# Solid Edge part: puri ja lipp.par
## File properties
Username: Kasutaja
Author: Kasutaja
Template: Iso Metric Part.par
Last saved by: Kasutaja
Revision: 12
Application: Solid Edge
Accuracy: 0,990
Face Style: Model Default
Fill Style: Normal
Coef. of Thermal Exp: 0.0
Thermal Conductivity: 0.0
Specific Heat: 0.0
Modulus of Elasticity: 0.0
Poisson's Ratio: 0.0
Yield Stress: 0.0
Ultimate Stress: 0.0
Elongation: 0.0
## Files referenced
..\Raemapuu.par.asm
?C:\Users\Kasutaja\Desktop\ema asjad\New folder\Raemapuu.par.asm
C:\Users\Kasutaja\Desktop\ema asjad\New folder\vedru.par
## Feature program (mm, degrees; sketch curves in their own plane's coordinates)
sketch for "unnamed Protrusion 1" plane through (0, 0, 0) normal (0, -1, 0) x-axis (1, 0, 0)
  line (-43.6871, 422.4607) -> (68.138, 376.9726)
  line (68.138, 376.9726) -> (-43.6871, 376.9726)
  line (-43.6871, 376.9726) -> (-43.6871, 422.4607)
extrude "unnamed Protrusion 1" add finite 3 along +normal
sketch for "ExtrudedCutout_1" #1 plane through (12.2254, 0, 399.7167) normal (0, 1, 0) x-axis (-1, 0, 0)
  circle centre (49.8132, 13.2316) radius 3
sketch for "ExtrudedCutout_1" #2 plane through (12.2254, 0, 399.7167) normal (0, 1, 0) x-axis (-1, 0, 0)
  circle centre (49.8132, -16.172) radius 3
extrude "ExtrudedCutout_1" cut finite 4 along -normal
sketch for "unnamed RevolvedProtrusion 1" plane through (12.2254, 0, 399.7167) normal (0, 1, 0) x-axis (1, 0, 0)
  line (-49.8823, 18.4105) -> (-49.8823, 13.9056)
revolve "unnamed RevolvedProtrusion 1" add finite 360 deg
thicken "Thicken_2"  Distance1 = 2 mm
sketch for "ExtrudedCutout_3" #1 plane through (0, -164.6196, 0) normal (0, -1, 0) x-axis (1, 0, 0)
sketch for "ExtrudedCutout_3" #2 plane through (0, -164.6196, 0) normal (0, -1, 0) x-axis (1, 0, 0)
  circle centre (-228.1109, 343.8791) radius 3
sketch for "ExtrudedCutout_3" #3 plane through (0, -164.6196, 0) normal (0, -1, 0) x-axis (1, 0, 0)
  circle centre (-184.0316, 343.8791) radius 3
sketch for "ExtrudedCutout_3" #4 plane through (0, -164.6196, 0) normal (0, -1, 0) x-axis (1, 0, 0)
  circle centre (-139.3041, 343.8791) radius 3
sketch for "ExtrudedCutout_3" #5 plane through (0, -164.6196, 0) normal (0, -1, 0) x-axis (1, 0, 0)
  circle centre (-94.5766, 343.2957) radius 3
sketch for "ExtrudedCutout_3" #6 plane through (0, -164.6196, 0) normal (0, -1, 0) x-axis (1, 0, 0)
  circle centre (-49.8491, 343.7819) radius 3
sketch for "ExtrudedCutout_3" #7 plane through (0, -164.6196, 0) normal (0, -1, 0) x-axis (1, 0, 0)
  circle centre (-5.2837, 343.7819) radius 3
sketch for "ExtrudedCutout_3" #8 plane through (0, -164.6196, 0) normal (0, -1, 0) x-axis (1, 0, 0)
  circle centre (39.4438, 343.7819) radius 3
sketch for "ExtrudedCutout_3" #9 plane through (0, -164.6196, 0) normal (0, -1, 0) x-axis (1, 0, 0)
  circle centre (83.6851, 343.7819) radius 3
sketch for "ExtrudedCutout_3" #10 plane through (0, -164.6196, 0) normal (0, -1, 0) x-axis (1, 0, 0)
  circle centre (128.4126, 343.1337) radius 3
sketch for "ExtrudedCutout_3" #11 plane through (0, -164.6196, 0) normal (0, -1, 0) x-axis (1, 0, 0)
  circle centre (171.3575, 344.9163) radius 3
extrude "ExtrudedCutout_3" cut finite 551.5036 along -normal  Profile_Plane1_Distance = 164.6196 mm
mirror "unnamed Mirror 1" of "unnamed RevolvedProtrusion 1" about plane through (0, 0, 398.4228) normal (0, 0, 1)
revolve "unnamed RevolvedProtrusion 2" add finite 360 deg
sketch for "unnamed Protrusion 2" #1 plane through (0, -100, 0) normal (0, -1, 0) x-axis (1, 0, 0)
sketch for "unnamed Protrusion 2" #2 plane through (0, -100, 0) normal (0, -1, 0) x-axis (1, 0, 0)
sketch for "unnamed Protrusion 2" #3 plane through (0, -100, 0) normal (0, -1, 0) x-axis (1, 0, 0)
sketch for "unnamed Protrusion 2" #4 plane through (0, -100, 0) normal (0, -1, 0) x-axis (1, 0, 0)
sketch for "unnamed Protrusion 2" #5 plane through (0, -100, 0) normal (0, -1, 0) x-axis (1, 0, 0)
sketch for "unnamed Protrusion 2" #6 plane through (0, -100, 0) normal (0, -1, 0) x-axis (1, 0, 0)
sketch for "unnamed Protrusion 2" #7 plane through (0, -100, 0) normal (0, -1, 0) x-axis (1, 0, 0)
sketch for "unnamed Protrusion 2" #8 plane through (0, -100, 0) normal (0, -1, 0) x-axis (1, 0, 0)
sketch for "unnamed Protrusion 2" #9 plane through (0, -100, 0) normal (0, -1, 0) x-axis (1, 0, 0)
sketch for "unnamed Protrusion 2" #10 plane through (0, -100, 0) normal (0, -1, 0) x-axis (1, 0, 0)
sketch for "unnamed Protrusion 2" #11 plane through (0, -100, 0) normal (0, -1, 0) x-axis (1, 0, 0)
sketch for "unnamed Protrusion 2" #12 plane through (0, -100, 0) normal (0, -1, 0) x-axis (1, 0, 0)
extrude "unnamed Protrusion 2" add along -normal
Other named dimensions: "OffsetSurface_1": Distance = 0.5 mm | "OffsetSurface_2": Distance = 0.001 mm
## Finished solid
Body 1: sheet body, 1 face, 6 edges, 6 vertices.
  Faces by surface: offset 1
  Edges by curve: curve on surface 6
Body 2: sheet body, 1 face, 6 edges, 6 vertices.
  Faces by surface: offset 1
  Edges by curve: curve on surface 6
Body 3: sheet body, 1 face, 4 edges, 4 vertices.
  Faces by surface: spline 1
  Edges by curve: line 2, spline 2
Body 4: solid body, 128 faces, 290 edges, 172 vertices, 14 separate solids.
  Faces by surface: plane 72, offset 21, cylinder 15, swept 12, spline 6, torus 2
  Edges by curve: intersection 182, line 88, curve on surface 9, circle 8, spline 3
Bounding box of the edges (mm; curved faces can reach further): 473.670 x 56.458 x 302.777, from (-297.1393, -47.3569, 119.6834) to (176.5304, 9.101, 422.4607).
Cylindrical faces by radius (mm): R3 x13, R9.101 x2
Toroidal faces (ring radius, tube radius in mm): R9.101 r2.2524 x2
Planar faces by outward normal: +x 17, +y 1, +z 13, -x 11, -y 1, -z 14, oblique 15
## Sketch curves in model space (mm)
spline (102.6112, -100, 229.2776) -> (96.9577, -100, 229.2776) -> (91.3041, -100, 229.2776)
spline (102.6112, -100, 222.0657) -> (102.6112, -100, 225.6717) -> (102.6112, -100, 229.2776)
spline (102.4309, -100, 240.7135) -> (77.2102, -100, 232.4814) -> (102.6112, -100, 222.0657)
spline (107.1701, -100, 241.9756) -> (104.8005, -100, 241.3445) -> (102.4309, -100, 240.7135)
spline (107.7625, -100, 219.5158) -> (71.9767, -100, 235.1939) -> (107.1701, -100, 241.9756)
spline (107.7625, -100, 233.8365) -> (107.7625, -100, 226.6762) -> (107.7625, -100, 219.5158)
spline (91.3041, -100, 233.8365) -> (99.5333, -100, 233.8365) -> (107.7625, -100, 233.8365)
spline (91.3041, -100, 229.2776) -> (91.3041, -100, 231.557) -> (91.3041, -100, 233.8365)
spline (60.4992, -100, 229.2776) -> (54.8456, -100, 229.2776) -> (49.192, -100, 229.2776)
spline (60.4992, -100, 222.0657) -> (60.4992, -100, 225.6717) -> (60.4992, -100, 229.2776)
spline (60.3189, -100, 240.7135) -> (35.0983, -100, 232.4755) -> (60.4992, -100, 222.0657)
spline (65.0323, -100, 241.9756) -> (62.6756, -100, 241.3445) -> (60.3189, -100, 240.7135)
spline (65.6505, -100, 219.5158) -> (29.8592, -100, 235.4281) -> (65.0323, -100, 241.9756)
spline (65.6505, -100, 233.8365) -> (65.6505, -100, 226.6762) -> (65.6505, -100, 219.5158)
spline (49.192, -100, 233.8365) -> (57.4213, -100, 233.8365) -> (65.6505, -100, 233.8365)
spline (49.192, -100, 229.2776) -> (49.192, -100, 231.557) -> (49.192, -100, 233.8365)
closed spline through (-7.2922, -100, 232.9093), (6.6013, -100, 217.9076), (19.1845, -100, 233.7056), (5.3058, -100, 249.0747)
closed spline through (-12.5723, -100, 232.9608), (5.3917, -100, 253.4792), (24.4844, -100, 234.0594), (6.3601, -100, 213.4929)
spline (-44.8196, -100, 248.595) -> (-44.8196, -100, 242.143) -> (-44.8196, -100, 235.691)
spline (-44.8196, -100, 235.691) -> (-24.369, -100, 242.3129) -> (-44.8196, -100, 248.595)
spline (-44.8196, -100, 214.1327) -> (-47.3952, -100, 214.1327) -> (-49.9709, -100, 214.1327)
spline (-44.8196, -100, 231.2866) -> (-44.8196, -100, 222.7096) -> (-44.8196, -100, 214.1327)
spline (-22.334, -100, 214.1327) -> (-30.9125, -100, 227.1807) -> (-44.8196, -100, 231.2866)
spline (-15.9206, -100, 214.1327) -> (-19.1273, -100, 214.1327) -> (-22.334, -100, 214.1327)
spline (-29.958, -100, 231.6729) -> (-22.0309, -100, 223.7457) -> (-15.9206, -100, 214.1327)
spline (-49.9709, -100, 252.8449) -> (-23.3958, -100, 250.9847) -> (-29.958, -100, 231.6729)
spline (-49.9709, -100, 214.1327) -> (-49.9709, -100, 233.4888) -> (-49.9709, -100, 252.8449)
spline (-81.3939, -100, 214.1327) -> (-83.9696, -100, 214.1327) -> (-86.5452, -100, 214.1327)
spline (-81.3939, -100, 227.5261) -> (-81.3939, -100, 220.8294) -> (-81.3939, -100, 214.1327)
spline (-75.032, -100, 233.682) -> (-78.213, -100, 230.604) -> (-81.3939, -100, 227.5261)
spline (-61.278, -100, 214.1327) -> (-68.155, -100, 223.9073) -> (-75.032, -100, 233.682)
spline (-54.5298, -100, 214.1327) -> (-57.9039, -100, 214.1327) -> (-61.278, -100, 214.1327)
spline (-71.4261, -100, 237.1591) -> (-62.978, -100, 225.6459) -> (-54.5298, -100, 214.1327)
spline (-55.251, -100, 252.8449) -> (-63.3385, -100, 245.002) -> (-71.4261, -100, 237.1591)
spline (-62.2053, -100, 252.8449) -> (-58.7281, -100, 252.8449) -> (-55.251, -100, 252.8449)
spline (-81.3939, -100, 233.682) -> (-71.7996, -100, 243.2634) -> (-62.2053, -100, 252.8449)
spline (-81.3939, -100, 252.8449) -> (-81.3939, -100, 243.2634) -> (-81.3939, -100, 233.682)
spline (-86.5452, -100, 252.8449) -> (-83.9696, -100, 252.8449) -> (-81.3939, -100, 252.8449)
spline (-86.5452, -100, 214.1327) -> (-86.5452, -100, 233.4888) -> (-86.5452, -100, 252.8449)
spline (-99.4493, -100, 241.5377) -> (-95.6892, -100, 231.4604) -> (-124.0726, -100, 226.6246)
spline (-94.5555, -100, 241.9498) -> (-97.0024, -100, 241.7438) -> (-99.4493, -100, 241.5377)
spline (-119.2819, -100, 227.0368) -> (-116.8807, -100, 234.2416) -> (-94.5555, -100, 241.9498)
spline (-124.0726, -100, 226.6246) -> (-121.6772, -100, 226.8307) -> (-119.2819, -100, 227.0368)
spline (-128.5027, -100, 214.1327) -> (-140.6083, -100, 214.1327) -> (-152.7139, -100, 214.1327)
spline (-128.5027, -100, 218.6916) -> (-128.5027, -100, 216.4122) -> (-128.5027, -100, 214.1327)
spline (-147.5884, -100, 218.6916) -> (-138.0456, -100, 218.6916) -> (-128.5027, -100, 218.6916)
spline (-147.5884, -100, 252.8449) -> (-147.5884, -100, 235.7682) -> (-147.5884, -100, 218.6916)
spline (-152.7139, -100, 252.8449) -> (-150.1512, -100, 252.8449) -> (-147.5884, -100, 252.8449)
spline (-152.7139, -100, 214.1327) -> (-152.7139, -100, 233.4888) -> (-152.7139, -100, 252.8449)
spline (-158.5865, -100, 214.1327) -> (-170.6921, -100, 214.1327) -> (-182.7977, -100, 214.1327)
spline (-158.5865, -100, 218.6916) -> (-158.5865, -100, 216.4122) -> (-158.5865, -100, 214.1327)
spline (-177.6721, -100, 218.6916) -> (-168.1293, -100, 218.6916) -> (-158.5865, -100, 218.6916)
spline (-177.6721, -100, 252.8449) -> (-177.6721, -100, 235.7682) -> (-177.6721, -100, 218.6916)
spline (-182.7977, -100, 252.8449) -> (-180.2349, -100, 252.8449) -> (-177.6721, -100, 252.8449)
spline (-182.7977, -100, 214.1327) -> (-182.7977, -100, 233.4888) -> (-182.7977, -100, 252.8449)
spline (-189.6232, -100, 214.1327) -> (-204.0597, -100, 214.1327) -> (-218.4963, -100, 214.1327)
spline (-189.6232, -100, 218.6916) -> (-189.6232, -100, 216.4122) -> (-189.6232, -100, 214.1327)
spline (-213.3707, -100, 218.6916) -> (-201.4969, -100, 218.6916) -> (-189.6232, -100, 218.6916)
spline (-213.3707, -100, 231.8532) -> (-213.3707, -100, 225.2724) -> (-213.3707, -100, 218.6916)
spline (-191.9413, -100, 231.8532) -> (-202.656, -100, 231.8532) -> (-213.3707, -100, 231.8532)
spline (-191.9413, -100, 236.4122) -> (-191.9413, -100, 234.1327) -> (-191.9413, -100, 231.8532)
spline (-213.3707, -100, 236.4122) -> (-202.656, -100, 236.4122) -> (-191.9413, -100, 236.4122)
spline (-213.3707, -100, 248.2602) -> (-213.3707, -100, 242.3362) -> (-213.3707, -100, 236.4122)
spline (-190.4989, -100, 248.2602) -> (-201.9348, -100, 248.2602) -> (-213.3707, -100, 248.2602)
spline (-190.4989, -100, 252.8449) -> (-190.4989, -100, 250.5525) -> (-190.4989, -100, 248.2602)
spline (-218.4963, -100, 252.8449) -> (-204.4976, -100, 252.8449) -> (-190.4989, -100, 252.8449)
spline (-218.4963, -100, 214.1327) -> (-218.4963, -100, 233.4888) -> (-218.4963, -100, 252.8449)
spline (-249.8678, -100, 214.1327) -> (-252.4306, -100, 214.1327) -> (-254.9934, -100, 214.1327)
spline (-249.8678, -100, 227.5261) -> (-249.8678, -100, 220.8294) -> (-249.8678, -100, 214.1327)
spline (-243.506, -100, 233.682) -> (-246.6869, -100, 230.604) -> (-249.8678, -100, 227.5261)
spline (-229.7519, -100, 214.1327) -> (-236.629, -100, 223.9073) -> (-243.506, -100, 233.682)
spline (-223.0037, -100, 214.1327) -> (-226.3778, -100, 214.1327) -> (-229.7519, -100, 214.1327)
spline (-239.9, -100, 237.1591) -> (-231.4519, -100, 225.6459) -> (-223.0037, -100, 214.1327)
spline (-223.7249, -100, 252.8449) -> (-231.8125, -100, 245.002) -> (-239.9, -100, 237.1591)
spline (-230.6534, -100, 252.8449) -> (-227.1892, -100, 252.8449) -> (-223.7249, -100, 252.8449)
spline (-249.8678, -100, 233.682) -> (-240.2606, -100, 243.2634) -> (-230.6534, -100, 252.8449)
spline (-249.8678, -100, 252.8449) -> (-249.8678, -100, 243.2634) -> (-249.8678, -100, 233.682)
spline (-254.9934, -100, 252.8449) -> (-252.4306, -100, 252.8449) -> (-249.8678, -100, 252.8449)
spline (-254.9934, -100, 214.1327) -> (-254.9934, -100, 233.4888) -> (-254.9934, -100, 252.8449)
line (-268.4696, 0, 120.9658) -> (176.5304, 0, 120.9658)
line (-268.4696, 0, 358.068) -> (176.5304, 0, 358.068)
line (-46.7579, 0, 381.7806) -> (-46.7579, 0, 389.2313)
arc centre (-37.6569, 0, 383.5586) radius 2.2524 from (-37.6569, 0, 381.3062) through (-35.4054, 0, 383.6253) to (-37.6569, 0, 385.811)
line (-37.6569, 0, 381.3062) -> (-37.6569, 0, 385.811)
circle centre (-37.5878, 0, 383.5447) radius 3
circle centre (-37.5878, 0, 412.9483) radius 3
line (-43.6871, 0, 376.9726) -> (-43.6871, 0, 422.4607)
line (-43.6871, 0, 422.4607) -> (68.138, 0, 376.9726)
line (68.138, 0, 376.9726) -> (-43.6871, 0, 376.9726)
line (-43.5991, 0, 421.9762) -> (-43.5991, 0, 467.4644)
line (-43.5991, 0, 467.4644) -> (68.226, 0, 421.9762)
line (68.226, 0, 421.9762) -> (-43.5991, 0, 421.9762)
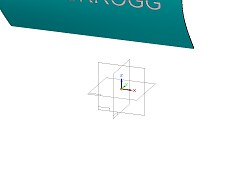
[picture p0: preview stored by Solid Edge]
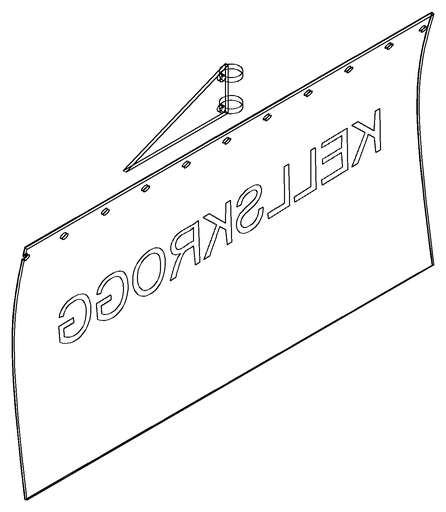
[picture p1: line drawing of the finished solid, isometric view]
